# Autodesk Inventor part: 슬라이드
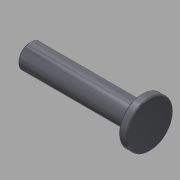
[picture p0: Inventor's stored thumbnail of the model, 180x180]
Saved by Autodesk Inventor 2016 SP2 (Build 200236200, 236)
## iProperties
Created: 2015-10
Part Number: 슬라이드
Document SubType Name: Modeling
Designer: mdu
Density: 7.86 g/cm^3
Material: 강철, 연강
Appearance: 강철 - 광택
Mass: 954.83 g
Surface Area: 210.251 cm^2
Volume: 121.48 cm^3
Author: mdu
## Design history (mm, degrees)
sketch "스케치1"
  geometry: L1 (-75, 162)-(-75, 58) reference; L2 (-148, 110)-(2, 110); L3 (-148, 110)-(-148, 125); L4 (-148, 125)-(-8, 125); L5 (-8, 125)-(-8, 139); L6 (-8, 139)-(2, 139); L7 (2, 139)-(2, 110); 2 further points
  constraints: 12 end point, 3 parallel, 3 perpendicular, 1 midpoint, 1 point on line
  dimensions: "d0" = 58 diameter of L6 L2; "d1" = 30 diameter of L4 L2; "d2" = 10 distance of L5.end L6.end; "d3" = 150 distance of L2.start L2.end; "d4" = 73 distance between parallel lines of L3 L1
revolve "회전1" sketch "스케치1" stored, may be unused: angle "d5" = 90 deg
hole "구멍1" diameter "d11" = 13.376; stored, may be unused: countersink angle "d15" = 90 deg, drill point angle "d17" = 118 deg; dims "d9" = 10, "d10" = 10, "d12" = 22, "d13" = 4, "d14" = 2, "d16" = 25
chamfer "모따기1" distance "d6" = 1; stored, may be unused: second distance "d7" = 2, angle "d8" = 45 deg
node "솔리드1"
node "참조1"
